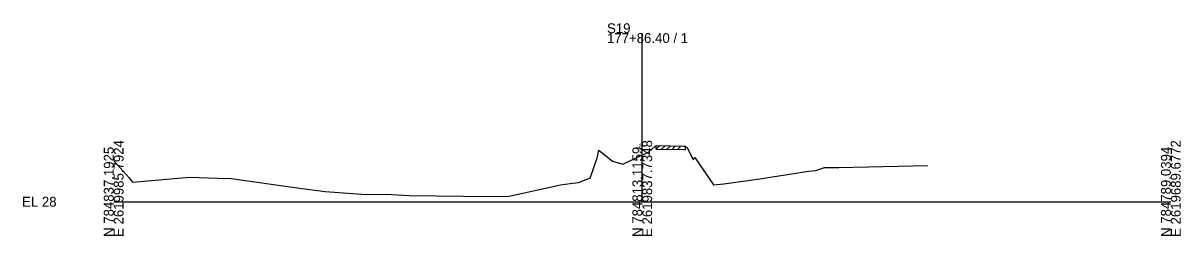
# Model space of a CAD drawing. Extents: x 1274 to 1603, y -10 to 1051.
# Drawn here: x 1274.3 to 1602.8, y 990.3 to 1050.7 of the extents above; entities that cross this region are included whole.
import ezdxf

# ---------------------------------------------------------------- set-up
doc = ezdxf.new("R2010")
doc.units = 0
for name, color, linetype in [('RD_GPK_XS_Cell', 7, 'Continuous'), ('RD_XS_ExGround', 7, 'Continuous'), ('RD_XS_ExPaveRet', 7, 'Continuous'), ('RD_XS_TX_Elev_EX', 7, 'Continuous')]:
    doc.layers.add(name, color=color, linetype=linetype)

msp = doc.modelspace()

# ---------------------------------------------------------------- linework, layer by layer
at = {"layer": 'RD_GPK_XS_Cell'}
for p, q in [((1450, 1000), (1450, 1047.86)), ((1300, 1000), (1450, 1000)), ((1450, 1000), (1600, 1000))]:
    msp.add_line(p, q, dxfattribs=at)
at = {"layer": 'RD_XS_ExGround'}
for p, q in [((1451.82, 1014.14), (1453.68, 1015.81)), ((1453.68, 1015.81), (1453.99, 1015.95)), ((1453.99, 1015.95), (1461.7, 1015.78)), ((1461.7, 1015.78), (1462.16, 1015.76)), ((1462.16, 1015.76), (1462.75, 1015.41)), ((1462.75, 1015.41), (1464.42, 1011.89)), ((1435.25, 1006.68), (1437.32, 1012.72)), ((1437.32, 1012.72), (1437.7, 1014.6)), ((1437.7, 1014.6), (1441.57, 1011.52)), ((1444.47, 1010.66), (1449.66, 1013.09)), ((1449.66, 1013.09), (1450, 1013.26)), ((1450, 1013.26), (1451.82, 1014.14)), ((1464.42, 1011.89), (1464.93, 1012.59)), ((1464.93, 1012.59), (1470.23, 1004.75)), ((1300, 1011.49), (1300.17, 1011.49)), ((1300.17, 1011.49), (1304.37, 1006.75)), ((1441.57, 1011.52), (1444.47, 1010.66)), ((1483.33, 1006.48), (1497.15, 1008.67)), ((1497.15, 1008.67), (1499.24, 1008.83)), ((1499.24, 1008.83), (1501.69, 1009.7)), ((1501.69, 1009.7), (1505.82, 1009.72)), ((1505.82, 1009.72), (1531.04, 1010.24)), ((1304.37, 1006.75), (1305.38, 1005.52)), ((1305.38, 1005.52), (1321.48, 1007.01)), ((1321.48, 1007.01), (1329.63, 1006.73)), ((1329.63, 1006.73), (1333.32, 1006.6)), ((1333.32, 1006.6), (1352.73, 1003.85)), ((1429.52, 1005.17), (1431.9, 1005.46)), ((1431.9, 1005.46), (1434.54, 1006.54)), ((1434.54, 1006.54), (1435.25, 1006.68)), ((1473.12, 1005.06), (1483.33, 1006.48)), ((1352.73, 1003.85), (1359.97, 1002.87)), ((1359.97, 1002.87), (1371.77, 1002.03)), ((1371.77, 1002.03), (1377.29, 1002.1)), ((1377.29, 1002.1), (1383.83, 1001.74)), ((1412.24, 1001.57), (1426.83, 1004.77)), ((1426.83, 1004.77), (1429.52, 1005.17)), ((1470.23, 1004.75), (1473.12, 1005.06)), ((1383.83, 1001.74), (1407.03, 1001.47)), ((1407.03, 1001.47), (1412.24, 1001.57))]:
    msp.add_line(p, q, dxfattribs=at)
at = {"layer": 'RD_XS_ExPaveRet'}
for p, q in [((1453.99, 1014.95), (1453.99, 1015.95)), ((1453.99, 1014.95), (1454.97, 1015.93)), ((1455.49, 1014.92), (1456.47, 1015.9)), ((1456.99, 1014.89), (1457.97, 1015.87)), ((1458.49, 1014.85), (1459.47, 1015.83)), ((1459.99, 1014.82), (1460.97, 1015.8)), ((1462.16, 1015.76), (1462.16, 1014.76)), ((1453.99, 1014.95), (1461.7, 1014.78)), ((1461.7, 1014.78), (1462.16, 1014.76))]:
    msp.add_line(p, q, dxfattribs=at)

# ---------------------------------------------------------------- texts
at = {"layer": 'RD_GPK_XS_Cell'}
for s, p in [('S19', (1440, 1047.86)), ('177+86.40 / 1', (1440, 1045.06)), ('EL 28', (1274, 998.6))]:
    msp.add_text(s, height=2.8, dxfattribs=at).set_placement(p)
for s, p in [('N 784837.1925', (1300, 990)), ('E 2619985.7924', (1302.8, 990)), ('N 784813.1159', (1450, 990)), ('E 2619837.7348', (1452.8, 990)), ('N 784789.0394', (1600, 990)), ('E 2619689.6772', (1602.8, 990))]:
    msp.add_text(s, height=2.8, rotation=90, dxfattribs=at).set_placement(p)
at = {"layer": 'RD_XS_TX_Elev_EX'}
msp.add_text('41.26', height=0.8, rotation=90, dxfattribs=at).set_placement((1449.9, 1013.76))

doc.saveas('drawing.dxf')
